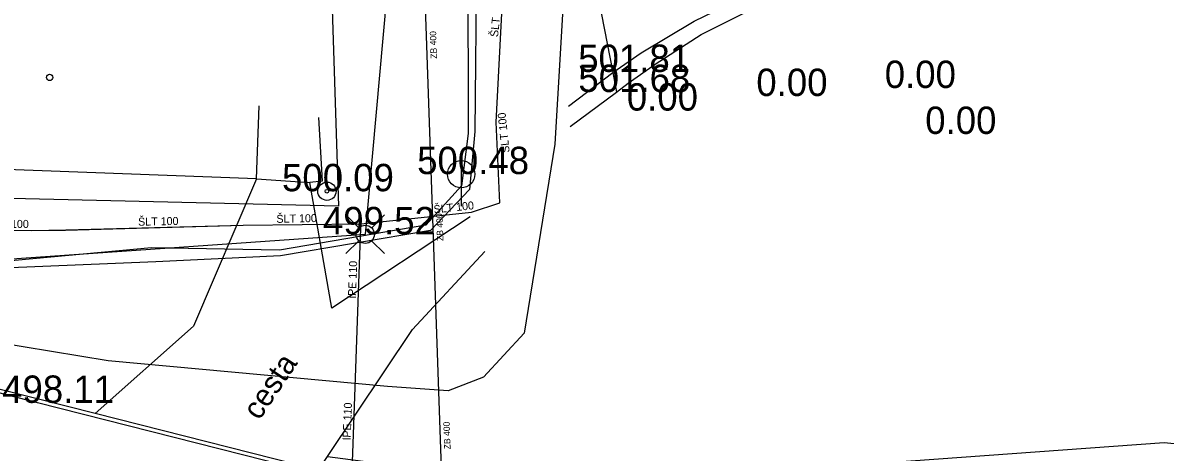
# Model space of a CAD drawing. Extents: x -669642 to -669119, y -1131006 to -1130466.
# Drawn here: x -669544 to -669512.68, y -1130600.19 to -1130588.42 of the extents above; entities that cross this region are included whole.
import ezdxf

# ---------------------------------------------------------------- set-up
doc = ezdxf.new("R2010")
doc.units = 0
for name, color, linetype in [('G_Bod_tecka', 7, 'Continuous'), ('G_Bod_vyska', 7, 'Continuous'), ('G_Breh_Teren', 7, 'Continuous'), ('G_Budovy-znacky', 7, 'Continuous'), ('G_Budovy_Objekty', 7, 'Continuous'), ('G_Cesty_Schody', 7, 'Continuous'), ('G_Plochy_zpevnene', 7, 'Continuous'), ('G_Ploty', 7, 'Continuous'), ('G_Ploty_vstupy', 7, 'Continuous'), ('G_Popisy_povrchu', 7, 'Continuous'), ('G_Site-kanalizace', 7, 'Continuous'), ('G_Site-plynovod', 7, 'Continuous'), ('G_Site-Sloupy', 7, 'Continuous'), ('G_Z_ELsilove_podz_kotovane', 7, 'Continuous'), ('G_Z_ELsilove_zrusene', 7, 'Continuous'), ('G_Z_KANAL_podz_kotovane', 7, 'Continuous'), ('G_Z_PLYNY_podz_geodeticky', 7, 'Continuous'), ('G_Z_PLYNY_podz_priblizne', 7, 'Continuous'), ('G_Z_VODA_podz_kotovane', 7, 'Continuous'), ('G_Zelen-okraj', 7, 'Continuous'), ('Vrstva 10', 7, 'Continuous'), ('Vrstva 26', 7, 'Continuous'), ('Vrstva 3', 7, 'Continuous'), ('Vrstva 4', 7, 'Continuous'), ('Vrstva 6', 7, 'Continuous'), ('Vrstva 7', 7, 'Continuous')]:
    doc.layers.add(name, color=color, linetype=linetype)

msp = doc.modelspace()

# ---------------------------------------------------------------- linework, layer by layer
at = {"layer": 'G_Bod_tecka'}
for p, q in [((-669527.79, -1130589.77), (-669527.79, -1130589.77)), ((-669527.71, -1130590.32), (-669527.71, -1130590.32)), ((-669519.59, -1130590.21), (-669519.59, -1130590.21)), ((-669523.11, -1130590.43), (-669523.11, -1130590.43)), ((-669526.66, -1130590.83), (-669526.66, -1130590.83)), ((-669518.48, -1130591.47), (-669518.48, -1130591.47)), ((-669531.98, -1130592.57), (-669531.98, -1130592.57)), ((-669535.66, -1130593.04), (-669535.66, -1130593.04)), ((-669534.61, -1130594.22), (-669534.61, -1130594.22)), ((-669543.6, -1130598.84), (-669543.6, -1130598.84))]:
    msp.add_line(p, q, dxfattribs=at)
at = {"layer": 'G_Breh_Teren'}
msp.add_lwpolyline([(-669535.64, -1130600.31), (-669530.61, -1130600.97), (-669521.04, -1130600.53), (-669512.71, -1130599.93), (-669495.59, -1130601.6), (-669485.9, -1130600.87), (-669475.24, -1130600.84), (-669462.05, -1130599.84), (-669445.96, -1130598.71)], dxfattribs=at)
at = {"layer": 'G_Budovy-znacky'}
msp.add_circle((-669543.26, -1130589.92), 0.0875, dxfattribs=at)
at = {"layer": 'G_Budovy_Objekty'}
for q in [(-669537.52, -1130590.7), (-669548.78, -1130592.28)]:
    msp.add_line((-669537.59, -1130592.7), q, dxfattribs=at)
at = {"layer": 'G_Cesty_Schody'}
for p, q in [((-669543.59, -1130598.84), (-669562.66, -1130593.99)), ((-669531.22, -1130601.97), (-669543.59, -1130598.84))]:
    msp.add_line(p, q, dxfattribs=at)
for points in [[(-669529.04, -1130590.71), (-669527.82, -1130589.79), (-669527.05, -1130589.25), (-669525.59, -1130588.38), (-669524.25, -1130587.72), (-669523.05, -1130587.21), (-669520.88, -1130586.42), (-669514.26, -1130584.33), (-669513.25, -1130584.01), (-669511.44, -1130583.55), (-669508.72, -1130582.91), (-669507.38, -1130582.51), (-669506.08, -1130581.99), (-669505.25, -1130581.55), (-669504.66, -1130581.17), (-669503.83, -1130580.54), (-669503.04, -1130579.85), (-669502.65, -1130579.49), (-669502.27, -1130579.13)], [(-669528.99, -1130591.27), (-669527.72, -1130590.32), (-669527.4, -1130590.08), (-669526.66, -1130589.56), (-669525.4, -1130588.74), (-669524.07, -1130588.08), (-669522.87, -1130587.58), (-669520.72, -1130586.8), (-669514.13, -1130584.71), (-669513.11, -1130584.39), (-669511.29, -1130583.94), (-669508.54, -1130583.31), (-669507.2, -1130582.9), (-669506.54, -1130582.65), (-669505.9, -1130582.35), (-669504.83, -1130581.74), (-669504.07, -1130581.21), (-669503, -1130580.34), (-669501.97, -1130579.41), (-669501.82, -1130579.27), (-669501.67, -1130579.13)], [(-669537.59, -1130592.7), (-669539.32, -1130596.74), (-669542.01, -1130599.13)], [(-669531.73, -1130593.74), (-669535.53, -1130596.24), (-669536.13, -1130592.8)], [(-669535.89, -1130600.68), (-669535.64, -1130600.31), (-669533.31, -1130596.83), (-669531.33, -1130594.69)]]:
    msp.add_lwpolyline(points, dxfattribs=at)
at = {"layer": 'G_Plochy_zpevnene'}
for p, q in [((-669535.89, -1130591.02), (-669535.79, -1130592.76)), ((-669543.57, -1130598.74), (-669562.59, -1130593.91))]:
    msp.add_line(p, q, dxfattribs=at)
msp.add_lwpolyline([(-669530.98, -1130601.93), (-669535.89, -1130600.68), (-669542.01, -1130599.13), (-669543.57, -1130598.74)], dxfattribs=at)
at = {"layer": 'G_Ploty'}
msp.add_line((-669535.79, -1130592.76), (-669536.13, -1130592.8), dxfattribs=at)
at = {"layer": 'G_Ploty_vstupy'}
msp.add_line((-669537.59, -1130592.7), (-669536.13, -1130592.8), dxfattribs=at)
at = {"layer": 'G_Site-kanalizace'}
msp.add_line((-669531.98, -1130592.195), (-669531.98, -1130593.445), dxfattribs=at)
msp.add_circle((-669531.98, -1130592.57), 0.375, dxfattribs=at)
at = {"layer": 'G_Site-plynovod'}
for p, q in [((-669535.142, -1130593.688), (-669534.787, -1130594.043)), ((-669534.433, -1130594.042), (-669534.079, -1130593.689)), ((-669534.787, -1130594.396), (-669535.14, -1130594.75)), ((-669534.434, -1130594.395), (-669534.079, -1130594.75))]:
    msp.add_line(p, q, dxfattribs=at)
msp.add_circle((-669534.61, -1130594.22), 0.25, dxfattribs=at)
at = {"layer": 'G_Site-Sloupy'}
for radius in [0.25, 0.05]:
    msp.add_circle((-669535.66, -1130593.04), radius, dxfattribs=at)
at = {"layer": 'G_Z_ELsilove_podz_kotovane'}
for points in [[(-669500.66, -1130540.32), (-669515.72, -1130539.79), (-669523.73, -1130540.47), (-669527.21, -1130540.62), (-669526.83, -1130552.4), (-669536.59, -1130554.49), (-669535.34, -1130593.45), (-669571.24, -1130592.61), (-669571.16, -1130579.46), (-669571.39, -1130578.6), (-669571.77, -1130566.09), (-669572.17, -1130554.22), (-669572.49, -1130545.57), (-669573.36, -1130532.75), (-669573.82, -1130523.78), (-669573.87, -1130520.47), (-669574.25, -1130510), (-669574.87, -1130499.19), (-669574.76, -1130498.82), (-669574.94, -1130498.48), (-669574.995, -1130497.207)], [(-669528.98, -1130584.47), (-669529.41, -1130591.75), (-669530.25, -1130596.93), (-669531.37, -1130598.14), (-669532.34, -1130598.51), (-669534, -1130598.39), (-669541.66, -1130597.69), (-669549.43, -1130596.41)]]:
    msp.add_lwpolyline(points, dxfattribs=at)
at = {"layer": 'G_Z_ELsilove_zrusene'}
for points in [[(-669530.61, -1130558.032), (-669530.827, -1130557.681), (-669531.033, -1130557.346), (-669531.823, -1130557.379), (-669532.71, -1130557.79), (-669532.718, -1130557.817), (-669533.046, -1130558.943), (-669533.078, -1130559.367), (-669532.72, -1130570.125), (-669532.669, -1130570.883), (-669532.584, -1130572.161), (-669532.516, -1130576.42), (-669532.194, -1130579.669), (-669531.745, -1130585.048), (-669531.795, -1130586.76), (-669531.792, -1130591.461), (-669531.975, -1130592.89), (-669532.953, -1130593.968), (-669536.96, -1130594.652), (-669540.471, -1130594.587), (-669544.605, -1130594.979)], [(-669530.61, -1130558.032), (-669530.827, -1130557.681), (-669531.033, -1130557.346), (-669531.823, -1130557.379), (-669532.71, -1130557.79), (-669532.718, -1130557.817), (-669533.046, -1130558.943), (-669533.078, -1130559.367), (-669532.72, -1130570.125), (-669532.669, -1130570.883), (-669532.584, -1130572.161), (-669532.516, -1130576.42), (-669532.194, -1130579.669), (-669531.745, -1130585.048), (-669531.795, -1130586.76), (-669531.792, -1130591.461), (-669531.975, -1130592.89), (-669532.953, -1130593.968), (-669536.96, -1130594.652), (-669540.471, -1130594.587), (-669544.605, -1130594.979)], [(-669530.772, -1130558.035), (-669530.987, -1130557.691), (-669531.109, -1130557.496), (-669531.742, -1130557.561), (-669532.289, -1130557.783), (-669532.589, -1130557.905), (-669532.833, -1130558.959), (-669532.855, -1130559.346), (-669532.378, -1130570.112), (-669532.414, -1130571.147), (-669532.45, -1130572.182), (-669532.322, -1130576.393), (-669532.023, -1130579.67), (-669531.525, -1130585.103), (-669531.562, -1130586.702), (-669531.602, -1130591.399), (-669531.749, -1130592.991), (-669532.819, -1130594.113), (-669536.931, -1130594.814), (-669540.354, -1130594.975), (-669544.555, -1130595.152)], [(-669530.772, -1130558.035), (-669530.987, -1130557.691), (-669531.109, -1130557.496), (-669531.742, -1130557.561), (-669532.289, -1130557.783), (-669532.589, -1130557.905), (-669532.833, -1130558.959), (-669532.855, -1130559.346), (-669532.378, -1130570.112), (-669532.414, -1130571.147), (-669532.45, -1130572.182), (-669532.322, -1130576.393), (-669532.023, -1130579.67), (-669531.525, -1130585.103), (-669531.562, -1130586.702), (-669531.602, -1130591.399), (-669531.749, -1130592.991), (-669532.819, -1130594.113), (-669536.931, -1130594.814), (-669540.354, -1130594.975), (-669544.555, -1130595.152)]]:
    msp.add_lwpolyline(points, dxfattribs=at)
at = {"layer": 'G_Z_KANAL_podz_kotovane'}
msp.add_line((-669534.11, -1130555.13), (-669532.28, -1130607.88), dxfattribs=at)
at = {"layer": 'G_Z_PLYNY_podz_geodeticky'}
msp.add_lwpolyline([(-669544.824, -1130594.927), (-669534.6, -1130594.22)], dxfattribs=at)
at = {"layer": 'G_Z_PLYNY_podz_priblizne'}
msp.add_lwpolyline([(-669534.6, -1130594.22), (-669532.44, -1130570.19), (-669532.79, -1130562.97), (-669532.9, -1130559.73), (-669532.74, -1130558.83)], dxfattribs=at)
at = {"layer": 'G_Z_VODA_podz_kotovane'}
for points in [[(-669534.72, -1130593.93), (-669531.7, -1130593.61), (-669530.92, -1130593.36), (-669531.02, -1130591.15), (-669530.85, -1130587.81), (-669531.17, -1130584.5), (-669531.56, -1130580.45), (-669532.36, -1130574.55), (-669533.32, -1130569.35), (-669533.9, -1130564.47), (-669534.9, -1130559.16), (-669535.11, -1130557.55), (-669535.24, -1130557.07), (-669535.45, -1130552.17), (-669535.51, -1130546.04), (-669535.63, -1130544.45)], [(-669565.81, -1130592.55), (-669565.44, -1130592.57), (-669563.99, -1130592.83), (-669562.57, -1130594.11), (-669558.51, -1130594.1), (-669543.76, -1130594.12), (-669542.82, -1130594.1), (-669537.96, -1130593.97), (-669534.72, -1130593.93)], [(-669535.82, -1130632.78), (-669535.8, -1130632.43), (-669535.6, -1130624.19), (-669535.33, -1130614.15), (-669535.11, -1130604.43), (-669534.95, -1130600.22), (-669534.74, -1130594.27), (-669534.72, -1130593.93)]]:
    msp.add_lwpolyline(points, dxfattribs=at)
at = {"layer": 'G_Zelen-okraj'}
msp.add_lwpolyline([(-669528.6, -1130585.8), (-669527.82, -1130589.79), (-669527.72, -1130590.32)], dxfattribs=at)
at = {"layer": 'Vrstva 10'}
msp.add_line((-669534.105, -1130555.135), (-669532.275, -1130607.883), dxfattribs=at)
at = {"layer": 'Vrstva 26'}
for points in [[(-669534.72, -1130593.93), (-669531.7, -1130593.61), (-669530.92, -1130593.36), (-669531.02, -1130591.15), (-669530.85, -1130587.81), (-669531.17, -1130584.5), (-669531.56, -1130580.45), (-669532.36, -1130574.55), (-669533.32, -1130569.35), (-669533.9, -1130564.47), (-669534.9, -1130559.16), (-669535.115, -1130557.546), (-669535.24, -1130557.07), (-669535.45, -1130552.17), (-669535.51, -1130546.04), (-669535.63, -1130544.45)], [(-669565.807, -1130592.554), (-669565.44, -1130592.573), (-669563.99, -1130592.83), (-669562.57, -1130594.11), (-669558.51, -1130594.1), (-669543.756, -1130594.116), (-669542.823, -1130594.103), (-669537.958, -1130593.974), (-669534.72, -1130593.93)], [(-669535.819, -1130632.776), (-669535.799, -1130632.427), (-669535.6, -1130624.19), (-669535.33, -1130614.15), (-669535.11, -1130604.43), (-669534.95, -1130600.22), (-669534.74, -1130594.27), (-669534.72, -1130593.93)]]:
    msp.add_lwpolyline(points, dxfattribs=at)
at = {"layer": 'Vrstva 6'}
msp.add_line((-669534.74, -1130594.27), (-669534.74, -1130594.27), dxfattribs=at)
at = {"layer": 'Vrstva 7'}
msp.add_line((-669543.756, -1130594.116), (-669543.756, -1130594.116), dxfattribs=at)

# ---------------------------------------------------------------- texts
at = {"layer": 'G_Bod_vyska'}
for s, p in [('501.81', (-669528.772, -1130589.77)), ('501.68', (-669528.768, -1130590.32)), ('0.00', (-669523.89, -1130590.43)), ('0.00', (-669520.37, -1130590.21)), ('0.00', (-669527.44, -1130590.83)), ('0.00', (-669519.26, -1130591.47)), ('500.48', (-669533.187, -1130592.57)), ('500.09', (-669536.891, -1130593.04)), ('499.52', (-669535.768, -1130594.22)), ('498.11', (-669544.563, -1130598.84))]:
    msp.add_text(s, height=0.75, dxfattribs=at).set_placement(p)
at = {"layer": 'G_Popisy_povrchu'}
msp.add_text('cesta', height=0.6, rotation=56.1961, dxfattribs=at).set_placement((-669537.514, -1130599.341))
at = {"layer": 'Vrstva 3'}
for rotation, p in [(91.9889, (-669532.641, -1130589.404)), (91.9889, (-669532.466, -1130594.4)), (92.0295, (-669532.269, -1130600.109))]:
    msp.add_text('ZB 400', height=0.1755, rotation=rotation, dxfattribs=at).set_placement(p)
at = {"layer": 'Vrstva 4'}
for s, rotation, p in [('ŠLT 100', 84.0288, (-669530.971, -1130588.821)), ('ŠLT 100', 95.9712, (-669530.65, -1130591.978)), ('ŠLT 100', 6.0615, (-669532.724, -1130593.648)), ('ŠLT 100', 1.1756, (-669540.835, -1130593.985)), ('ŠLT 100', 1.1905, (-669537.043, -1130593.907)), ('lPE 110', 87.9202, (-669534.867, -1130595.978)), ('lPE 110', 87.9202, (-669535.01, -1130599.862))]:
    msp.add_text(s, height=0.2194, rotation=rotation, dxfattribs=at).set_placement(p)
msp.add_text('ŠLT 100', height=0.2194, dxfattribs=at).set_placement((-669544.941, -1130594.045))

doc.saveas('drawing.dxf')
